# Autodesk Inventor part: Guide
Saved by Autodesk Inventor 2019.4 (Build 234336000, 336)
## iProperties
Created: 2021-08
Part Number: Guide
Material: Generic
Document SubType Name: Modeling
Designer: Administrator
Density: 1 g/cm^3
Appearance: Default
Title: Guide v17
Author: Administrator
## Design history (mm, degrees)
feature "Body1"
body "Solid1"
